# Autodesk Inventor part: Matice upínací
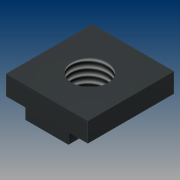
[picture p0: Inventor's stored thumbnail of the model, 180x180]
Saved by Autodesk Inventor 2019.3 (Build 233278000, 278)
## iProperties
Created: 2019-03
Part Number: Matice upínací
Material: Železo, lité
Document SubType Name: Modeling
Designer: B-hon
Density: 7.15 g/cm^3
Appearance: Železo – šedé
Author: B-hon
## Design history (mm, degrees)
sketch "Náčrt1"
  geometry: L1 (19, 0)-(19, 4.5); L2 (19, 4.5)-(0, 4.5); L3 (0, 4.5)-(0, 0); L4 (14.5, 0)-(14.5, -2.5); L5 (14.5, -2.5)-(4.5, -2.5); L6 (4.5, -2.5)-(4.5, 0); L7 (0, 0)-(4.5, 0); L8 (14.5, 0)-(19, 0)
  constraints: 16 end point, 4 parallel, 2 horizontal, 2 perpendicular
  dimensions: "d0" = 19 distance of L2.end L1.end; "d1" = 4.5 distance of L1.end L1.start; "d2" = 10 distance of L4.end L5.end; "d3" = 2.5 distance of L5.end L6.end; "d4" = 4.5 distance between parallel lines of L3 L6
extrude "Vysunutí1" new body sketch "Náčrt1" distance "d5" = 20; taper "d6" = 0 deg
sketch "Náčrt3"
  geometry: L1 (19, 0)-(19, -20) reference; L2 (19, -20)-(0, -20) reference; 2 further points
  dimensions: "d7" = 9.5 distance from line of L1 point (9.5, -10); "d8" = 10 distance from line of L2 point (9.5, -10)
hole "Díra1" sketch "Náčrt3" at (9.5, -10) diameter "d9" = 8.376; stored, may be unused: countersink angle "d13" = 90 deg, drill point angle "d15" = 118 deg; dims "d10" = 20, "d11" = 4, "d12" = 2, "d14" = 27.3
node "Těleso1"
